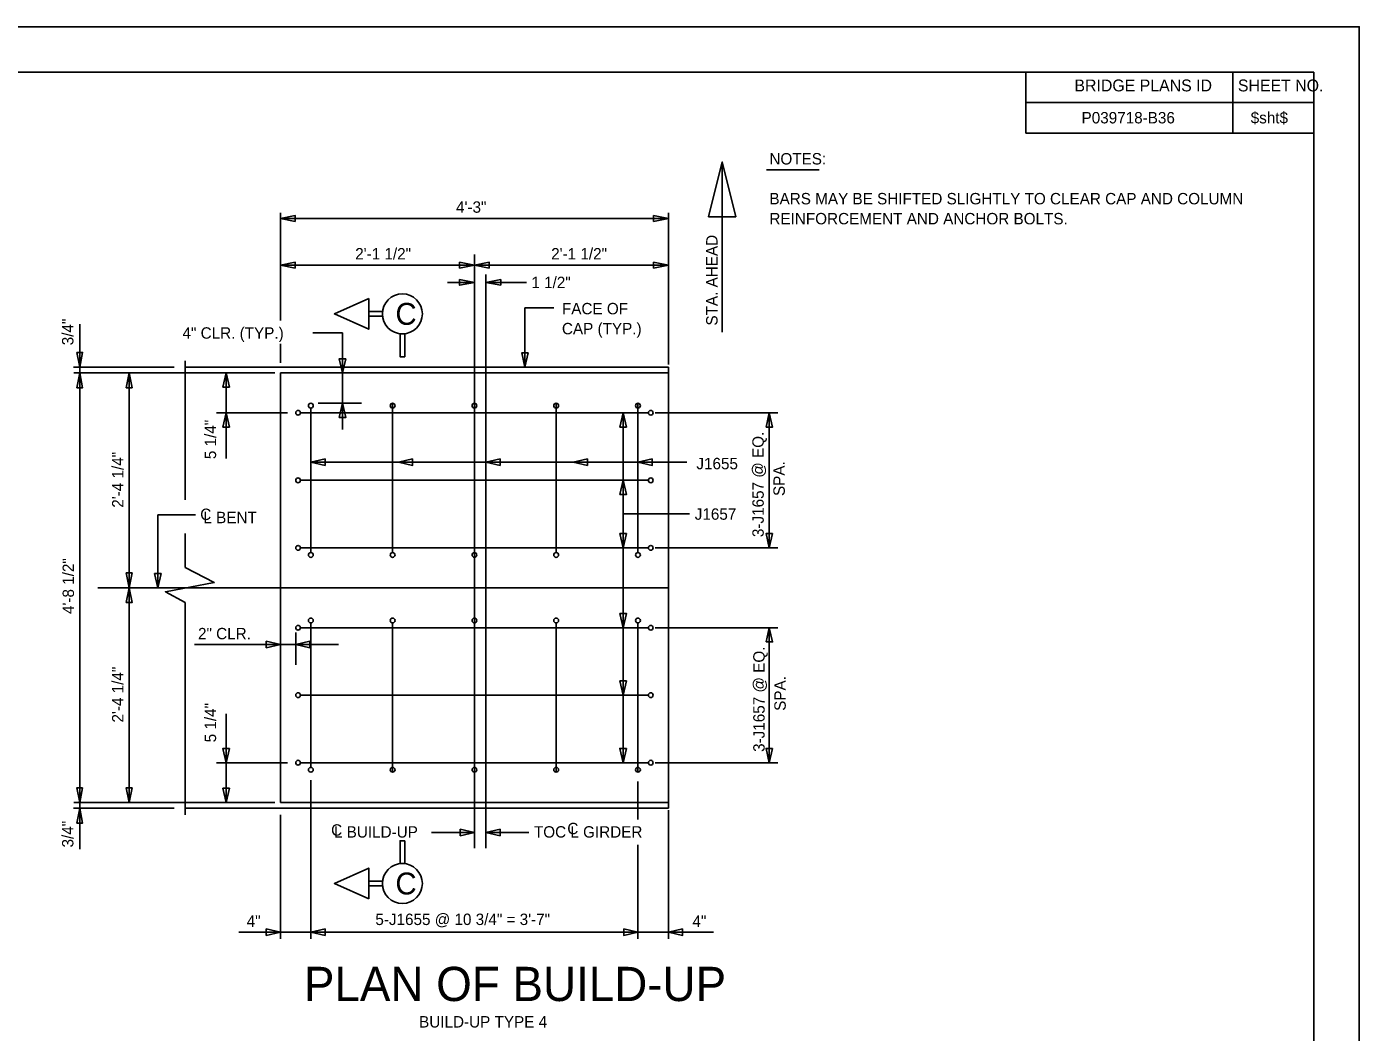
# Model space of a CAD drawing. Extents: x 1970675.2 to 1970711.3, y 796145.2 to 796167.2.
# Drawn here: x 1970696.64 to 1970711.24, y 796156.23 to 796167.25 of the extents above; entities that cross this region are included whole.
import ezdxf

# ---------------------------------------------------------------- set-up
doc = ezdxf.new("R2010")
doc.units = 0
for name, color, linetype in [('BR_AUTO DIMENSION', 7, 'Continuous'), ('BR_BORDER LINES', 7, 'Continuous'), ('BR_CENTER LINES', 7, 'Continuous'), ('BR_CONCRETE', 7, 'Continuous'), ('BR_REBAR', 7, 'Continuous'), ('BR_TEXT', 7, 'Continuous'), ('Default', 7, 'Continuous'), ('Level 31', 7, 'Continuous')]:
    doc.layers.add(name, color=color, linetype=linetype)

msp = doc.modelspace()

# ---------------------------------------------------------------- linework, layer by layer
at = {"layer": 'BR_AUTO DIMENSION'}
for p, q in [((1970704.256, 796165.764), (1970704.256, 796163.9)), ((1970704.74, 796165.678), (1970705.319, 796165.678)), ((1970699.416, 796164.025), (1970699.416, 796165.207)), ((1970703.666, 796163.546), (1970703.666, 796165.207)), ((1970699.416, 796165.145), (1970703.666, 796165.145)), ((1970701.541, 796164.751), (1970701.541, 796164.168)), ((1970699.416, 796164.632), (1970701.666, 796164.632)), ((1970703.666, 796164.632), (1970701.666, 796164.632)), ((1970701.246, 796164.444), (1970701.541, 796164.444)), ((1970701.666, 796164.525), (1970701.666, 796164.066)), ((1970701.666, 796164.444), (1970702.11, 796164.444)), ((1970702.095, 796164.165), (1970702.095, 796163.515)), ((1970702.095, 796164.165), (1970702.412, 796164.165)), ((1970697.217, 796163.452), (1970697.217, 796163.985)), ((1970700.096, 796163.89), (1970699.772, 796163.89)), ((1970700.096, 796162.831), (1970700.096, 796163.89)), ((1970699.416, 796163.562), (1970699.416, 796163.771)), ((1970698.251, 796163.515), (1970697.15, 796163.515)), ((1970699.354, 796163.452), (1970697.154, 796163.452)), ((1970697.217, 796158.744), (1970697.217, 796163.452)), ((1970697.759, 796163.452), (1970697.759, 796161.098)), ((1970698.821, 796163.452), (1970698.821, 796162.513)), ((1970699.828, 796163.119), (1970700.303, 796163.119)), ((1970699.495, 796163.015), (1970698.714, 796163.015)), ((1970703.17, 796163.015), (1970703.17, 796159.181)), ((1970703.521, 796163.015), (1970704.864, 796163.015)), ((1970704.772, 796161.535), (1970704.772, 796163.015)), ((1970699.749, 796162.474), (1970703.87, 796162.474)), ((1970698.073, 796161.897), (1970698.073, 796161.098)), ((1970698.485, 796161.897), (1970698.073, 796161.897)), ((1970703.17, 796161.908), (1970703.899, 796161.908)), ((1970703.521, 796161.535), (1970704.864, 796161.535)), ((1970697.702, 796161.098), (1970697.838, 796161.098)), ((1970697.759, 796161.098), (1970697.759, 796158.744)), ((1970703.521, 796160.66), (1970704.864, 796160.66)), ((1970704.772, 796159.181), (1970704.772, 796160.66)), ((1970699.583, 796160.608), (1970699.583, 796160.252)), ((1970700.051, 796160.476), (1970698.475, 796160.476)), ((1970698.821, 796158.744), (1970698.821, 796159.718)), ((1970699.495, 796159.181), (1970698.714, 796159.181)), ((1970703.521, 796159.181), (1970704.864, 796159.181)), ((1970699.749, 796158.988), (1970699.749, 796157.249)), ((1970703.333, 796158.975), (1970703.333, 796158.557)), ((1970699.354, 796158.744), (1970697.154, 796158.744)), ((1970697.217, 796158.744), (1970697.217, 796158.233)), ((1970698.251, 796158.681), (1970697.15, 796158.681)), ((1970699.416, 796158.61), (1970699.416, 796157.249)), ((1970703.666, 796158.661), (1970703.666, 796157.249)), ((1970701.541, 796158.415), (1970701.07, 796158.415)), ((1970701.666, 796158.415), (1970702.137, 796158.415)), ((1970703.333, 796158.281), (1970703.333, 796157.249)), ((1970698.96, 796157.324), (1970704.162, 796157.324))]:
    msp.add_line(p, q, dxfattribs=at)
for points in [[(1970699.579, 796165.113), (1970699.416, 796165.145), (1970699.579, 796165.176)], [(1970703.504, 796165.176), (1970703.666, 796165.145), (1970703.504, 796165.113)], [(1970699.579, 796164.601), (1970699.416, 796164.632), (1970699.579, 796164.664)], [(1970701.379, 796164.664), (1970701.541, 796164.632), (1970701.379, 796164.601)], [(1970701.704, 796164.601), (1970701.541, 796164.632), (1970701.704, 796164.664)], [(1970703.504, 796164.664), (1970703.666, 796164.632), (1970703.504, 796164.601)], [(1970701.379, 796164.475), (1970701.541, 796164.444), (1970701.379, 796164.412)], [(1970701.829, 796164.412), (1970701.666, 796164.444), (1970701.829, 796164.475)], [(1970697.186, 796163.677), (1970697.217, 796163.515), (1970697.248, 796163.677)], [(1970700.132, 796163.608), (1970700.096, 796163.452), (1970700.06, 796163.608)], [(1970702.131, 796163.671), (1970702.095, 796163.515), (1970702.059, 796163.671)], [(1970697.186, 796163.29), (1970697.217, 796163.452), (1970697.248, 796163.29)], [(1970697.727, 796163.29), (1970697.759, 796163.452), (1970697.79, 796163.29)], [(1970698.857, 796163.296), (1970698.821, 796163.452), (1970698.785, 796163.296)], [(1970700.06, 796162.963), (1970700.096, 796163.119), (1970700.132, 796162.963)], [(1970698.857, 796162.859), (1970698.821, 796163.015), (1970698.785, 796162.859)], [(1970703.134, 796162.859), (1970703.17, 796163.015), (1970703.206, 796162.859)], [(1970704.736, 796162.859), (1970704.772, 796163.015), (1970704.808, 796162.859)], [(1970699.905, 796162.51), (1970699.749, 796162.474), (1970699.905, 796162.438)], [(1970700.864, 796162.51), (1970700.708, 796162.474), (1970700.864, 796162.438)], [(1970701.822, 796162.51), (1970701.666, 796162.474), (1970701.822, 796162.438)], [(1970702.78, 796162.51), (1970702.624, 796162.474), (1970702.78, 796162.438)], [(1970703.489, 796162.51), (1970703.333, 796162.474), (1970703.489, 796162.438)], [(1970703.134, 796162.119), (1970703.17, 796162.275), (1970703.206, 796162.119)], [(1970703.134, 796161.691), (1970703.17, 796161.535), (1970703.206, 796161.691)], [(1970704.808, 796161.691), (1970704.772, 796161.535), (1970704.736, 796161.691)], [(1970697.79, 796161.26), (1970697.759, 796161.098), (1970697.727, 796161.26)], [(1970698.109, 796161.254), (1970698.073, 796161.098), (1970698.037, 796161.254)], [(1970697.727, 796160.935), (1970697.759, 796161.098), (1970697.79, 796160.935)], [(1970703.134, 796160.816), (1970703.17, 796160.66), (1970703.206, 796160.816)], [(1970704.736, 796160.504), (1970704.772, 796160.66), (1970704.808, 796160.504)], [(1970699.26, 796160.44), (1970699.416, 796160.476), (1970699.26, 796160.512)], [(1970699.739, 796160.512), (1970699.583, 796160.476), (1970699.739, 796160.44)], [(1970703.134, 796160.077), (1970703.17, 796159.921), (1970703.206, 796160.077)], [(1970698.857, 796159.337), (1970698.821, 796159.181), (1970698.785, 796159.337)], [(1970703.206, 796159.337), (1970703.17, 796159.181), (1970703.134, 796159.337)], [(1970704.808, 796159.337), (1970704.772, 796159.181), (1970704.736, 796159.337)], [(1970697.248, 796158.906), (1970697.217, 796158.744), (1970697.186, 796158.906)], [(1970697.79, 796158.906), (1970697.759, 796158.744), (1970697.727, 796158.906)], [(1970698.857, 796158.9), (1970698.821, 796158.744), (1970698.785, 796158.9)], [(1970697.186, 796158.519), (1970697.217, 796158.681), (1970697.248, 796158.519)], [(1970701.385, 796158.379), (1970701.541, 796158.415), (1970701.385, 796158.451)], [(1970701.822, 796158.379), (1970701.666, 796158.415), (1970701.822, 796158.451)], [(1970699.26, 796157.36), (1970699.416, 796157.324), (1970699.26, 796157.288)], [(1970699.905, 796157.288), (1970699.749, 796157.324), (1970699.905, 796157.36)], [(1970703.177, 796157.36), (1970703.333, 796157.324), (1970703.177, 796157.288)], [(1970703.822, 796157.36), (1970703.666, 796157.324), (1970703.822, 796157.288)]]:
    msp.add_lwpolyline(points, close=True, dxfattribs=at)
at = {"layer": 'BR_BORDER LINES'}
for p, q in [((1970710.736, 796166.746), (1970677.07, 796166.746)), ((1970707.584, 796166.08), (1970707.584, 796166.746)), ((1970709.85, 796166.08), (1970709.85, 796166.746)), ((1970710.736, 796145.746), (1970710.736, 796166.746)), ((1970707.584, 796166.417), (1970710.736, 796166.417)), ((1970709.85, 796166.417), (1970710.736, 796166.417)), ((1970710.736, 796166.08), (1970707.584, 796166.08))]:
    msp.add_line(p, q, dxfattribs=at)
at = {"layer": 'BR_CENTER LINES'}
for p, q in [((1970701.666, 796164.531), (1970701.666, 796164.179)), ((1970701.541, 796164.168), (1970701.541, 796158.243)), ((1970701.666, 796164.066), (1970701.666, 796158.243)), ((1970697.417, 796161.098), (1970703.666, 796161.098))]:
    msp.add_line(p, q, dxfattribs=at)
at = {"layer": 'BR_CONCRETE'}
for p, q in [((1970698.372, 796163.515), (1970703.666, 796163.515)), ((1970699.416, 796163.452), (1970699.416, 796158.744)), ((1970699.416, 796163.452), (1970703.666, 796163.452)), ((1970703.666, 796163.515), (1970703.666, 796158.681)), ((1970699.416, 796161.098), (1970703.666, 796161.098)), ((1970699.416, 796158.744), (1970703.666, 796158.744)), ((1970698.372, 796158.681), (1970703.666, 796158.681))]:
    msp.add_line(p, q, dxfattribs=at)
at = {"layer": 'BR_REBAR'}
for p, q in [((1970700.645, 796161.483), (1970700.645, 796163.119)), ((1970701.541, 796161.483), (1970701.541, 796163.119)), ((1970702.437, 796161.483), (1970702.437, 796163.119)), ((1970703.333, 796161.483), (1970703.333, 796163.119)), ((1970699.635, 796163.015), (1970703.447, 796163.015)), ((1970699.749, 796161.483), (1970699.749, 796163.067)), ((1970699.635, 796162.275), (1970703.447, 796162.275)), ((1970699.635, 796161.535), (1970703.447, 796161.535)), ((1970699.635, 796160.66), (1970703.447, 796160.66)), ((1970699.749, 796160.713), (1970699.749, 796159.129)), ((1970700.645, 796160.713), (1970700.645, 796159.077)), ((1970701.541, 796160.713), (1970701.541, 796159.077)), ((1970702.437, 796160.713), (1970702.437, 796159.077)), ((1970703.333, 796160.713), (1970703.333, 796159.077)), ((1970699.635, 796159.921), (1970703.447, 796159.921)), ((1970699.635, 796159.181), (1970703.447, 796159.181))]:
    msp.add_line(p, q, dxfattribs=at)
for centre, radius in [((1970699.749, 796163.093), 0.0261), ((1970700.645, 796163.093), 0.0261), ((1970701.541, 796163.093), 0.0261), ((1970702.437, 796163.093), 0.0261), ((1970703.333, 796163.093), 0.0261), ((1970699.609, 796163.015), 0.026), ((1970703.473, 796163.015), 0.026), ((1970699.609, 796162.275), 0.026), ((1970703.473, 796162.275), 0.026), ((1970699.609, 796161.535), 0.026), ((1970703.473, 796161.535), 0.026), ((1970699.749, 796161.457), 0.0261), ((1970700.645, 796161.457), 0.0261), ((1970701.541, 796161.457), 0.0261), ((1970702.437, 796161.457), 0.0261), ((1970703.333, 796161.457), 0.0261), ((1970699.609, 796160.66), 0.026), ((1970699.749, 796160.739), 0.0261), ((1970700.645, 796160.739), 0.0261), ((1970701.541, 796160.739), 0.0261), ((1970702.437, 796160.739), 0.0261), ((1970703.333, 796160.739), 0.0261), ((1970703.473, 796160.66), 0.026), ((1970699.609, 796159.921), 0.026), ((1970703.473, 796159.921), 0.026), ((1970699.609, 796159.181), 0.026), ((1970703.473, 796159.181), 0.026), ((1970699.749, 796159.103), 0.0261), ((1970700.645, 796159.103), 0.0261), ((1970701.541, 796159.103), 0.0261), ((1970702.437, 796159.103), 0.0261), ((1970703.333, 796159.103), 0.0261)]:
    msp.add_circle(centre, radius, dxfattribs=at)
at = {"layer": 'BR_TEXT'}
for points in [[(1970700.383, 796164.267), (1970700.008, 796164.099), (1970700.383, 796163.93)], [(1970700.533, 796164.074), (1970700.383, 796164.074), (1970700.383, 796164.124), (1970700.533, 796164.124)], [(1970700.777, 796163.629), (1970700.727, 796163.629), (1970700.727, 796163.88), (1970700.777, 796163.88)], [(1970700.777, 796158.326), (1970700.727, 796158.326), (1970700.727, 796158.076), (1970700.777, 796158.076)], [(1970700.383, 796157.688), (1970700.008, 796157.857), (1970700.383, 796158.026)], [(1970700.533, 796157.882), (1970700.383, 796157.882), (1970700.383, 796157.832), (1970700.533, 796157.832)]]:
    msp.add_lwpolyline(points, close=True, dxfattribs=at)
for centre in [(1970700.752, 796164.099), (1970700.752, 796157.857)]:
    msp.add_circle(centre, 0.219, dxfattribs=at)
at = {"layer": 'Default'}
for p, q in [((1970698.372, 796163.583), (1970698.372, 796162.063)), ((1970698.372, 796161.692), (1970698.372, 796161.319)), ((1970698.372, 796160.936), (1970698.372, 796158.609))]:
    msp.add_line(p, q, dxfattribs=at)
msp.add_lwpolyline([(1970704.406, 796165.164), (1970704.256, 796165.764), (1970704.106, 796165.164)], close=True, dxfattribs=at)
msp.add_lwpolyline([(1970698.372, 796160.936), (1970698.155, 796161.054), (1970698.691, 796161.154), (1970698.372, 796161.319)], dxfattribs=at)
at = {"layer": 'Level 31'}
msp.add_lwpolyline([(1970675.236, 796145.246), (1970711.236, 796145.246), (1970711.236, 796167.246), (1970675.236, 796167.246)], close=True, dxfattribs=at)

# ---------------------------------------------------------------- texts
at = {"layer": 'BR_AUTO DIMENSION'}
for s, p in [('NOTES:', (1970704.773, 796165.736)), ('4\'-3"', (1970701.34, 796165.207)), ('BARS MAY BE SHIFTED SLIGHTLY TO CLEAR CAP AND COLUMN', (1970704.773, 796165.299)), ('REINFORCEMENT AND ANCHOR BOLTS.', (1970704.773, 796165.08)), ('2\'-1 1/2"', (1970700.235, 796164.695)), ('2\'-1 1/2"', (1970702.382, 796164.695)), ('1 1/2"', (1970702.165, 796164.381)), ('FACE OF', (1970702.5, 796164.094)), ('CAP (TYP.)', (1970702.5, 796163.875)), ('4" CLR. (TYP.)', (1970698.343, 796163.827)), ('J1655', (1970703.973, 796162.396)), ('J1657', (1970703.955, 796161.843)), ('2" CLR.', (1970698.513, 796160.533)), ('C', (1970699.971, 796158.381)), ('L BUILD-UP', (1970700.002, 796158.36)), ('TOC L GIRDER', (1970702.193, 796158.36)), ('C', (1970702.559, 796158.397)), ('5-J1655 @ 10 3/4" = 3\'-7"', (1970700.456, 796157.402)), ('BUILD-UP TYPE 4', (1970700.935, 796156.279))]:
    msp.add_text(s, height=0.125, dxfattribs=at).set_placement(p)
for s, rotation, p in [('STA. AHEAD', 90, (1970704.205, 796163.971)), ('3-J1657 @ EQ. ', 90, (1970704.711, 796161.653)), ('2\'-4 1/4"', 90, (1970697.696, 796161.975)), ('SPA. ', 90, (1970704.942, 796162.103)), ('4\'-8 1/2"', 90, (1970697.154, 796160.81)), ('3-J1657 @ EQ. ', 90, (1970704.721, 796159.299)), ('2\'-4 1/4"', 90, (1970697.696, 796159.621)), ('SPA. ', 90, (1970704.952, 796159.749)), ('4"', 360, (1970699.046, 796157.382)), ('4"', 360, (1970703.93, 796157.382))]:
    msp.add_text(s, height=0.125, rotation=rotation, dxfattribs=at).set_placement(p)
at = {"layer": 'BR_TEXT'}
for s, height, p in [('BRIDGE PLANS ID', 0.13, (1970708.115, 796166.537)), ('SHEET NO.', 0.13, (1970709.906, 796166.537)), ('P039718-B36', 0.125, (1970708.193, 796166.186)), ('$sht$', 0.125, (1970710.046, 796166.186)), ('C', 0.24, (1970700.676, 796163.979)), ('C', 0.24, (1970700.676, 796157.737)), ('PLAN OF BUILD-UP', 0.375, (1970699.673, 796156.569))]:
    msp.add_text(s, height=height, dxfattribs=at).set_placement(p)
for s, rotation, p in [('3/4"', 90, (1970697.148, 796163.755)), ('5 1/4"', 90, (1970698.711, 796162.507)), ('C', 360, (1970698.537, 796161.84)), ('L BENT', 360, (1970698.572, 796161.805)), ('5 1/4"', 90, (1970698.711, 796159.404)), ('3/4"', 90, (1970697.148, 796158.252))]:
    msp.add_text(s, height=0.125, rotation=rotation, dxfattribs=at).set_placement(p)

doc.saveas('drawing.dxf')
